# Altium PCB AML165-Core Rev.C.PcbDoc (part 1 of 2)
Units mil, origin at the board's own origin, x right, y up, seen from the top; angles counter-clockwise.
Board outline 3307.09 x 2047.24 mil, 2 copper layers (Top Layer, Bottom Layer), stack 12.8 mil thick; 150 components, 70 nets, 398 pads, 304 vias.
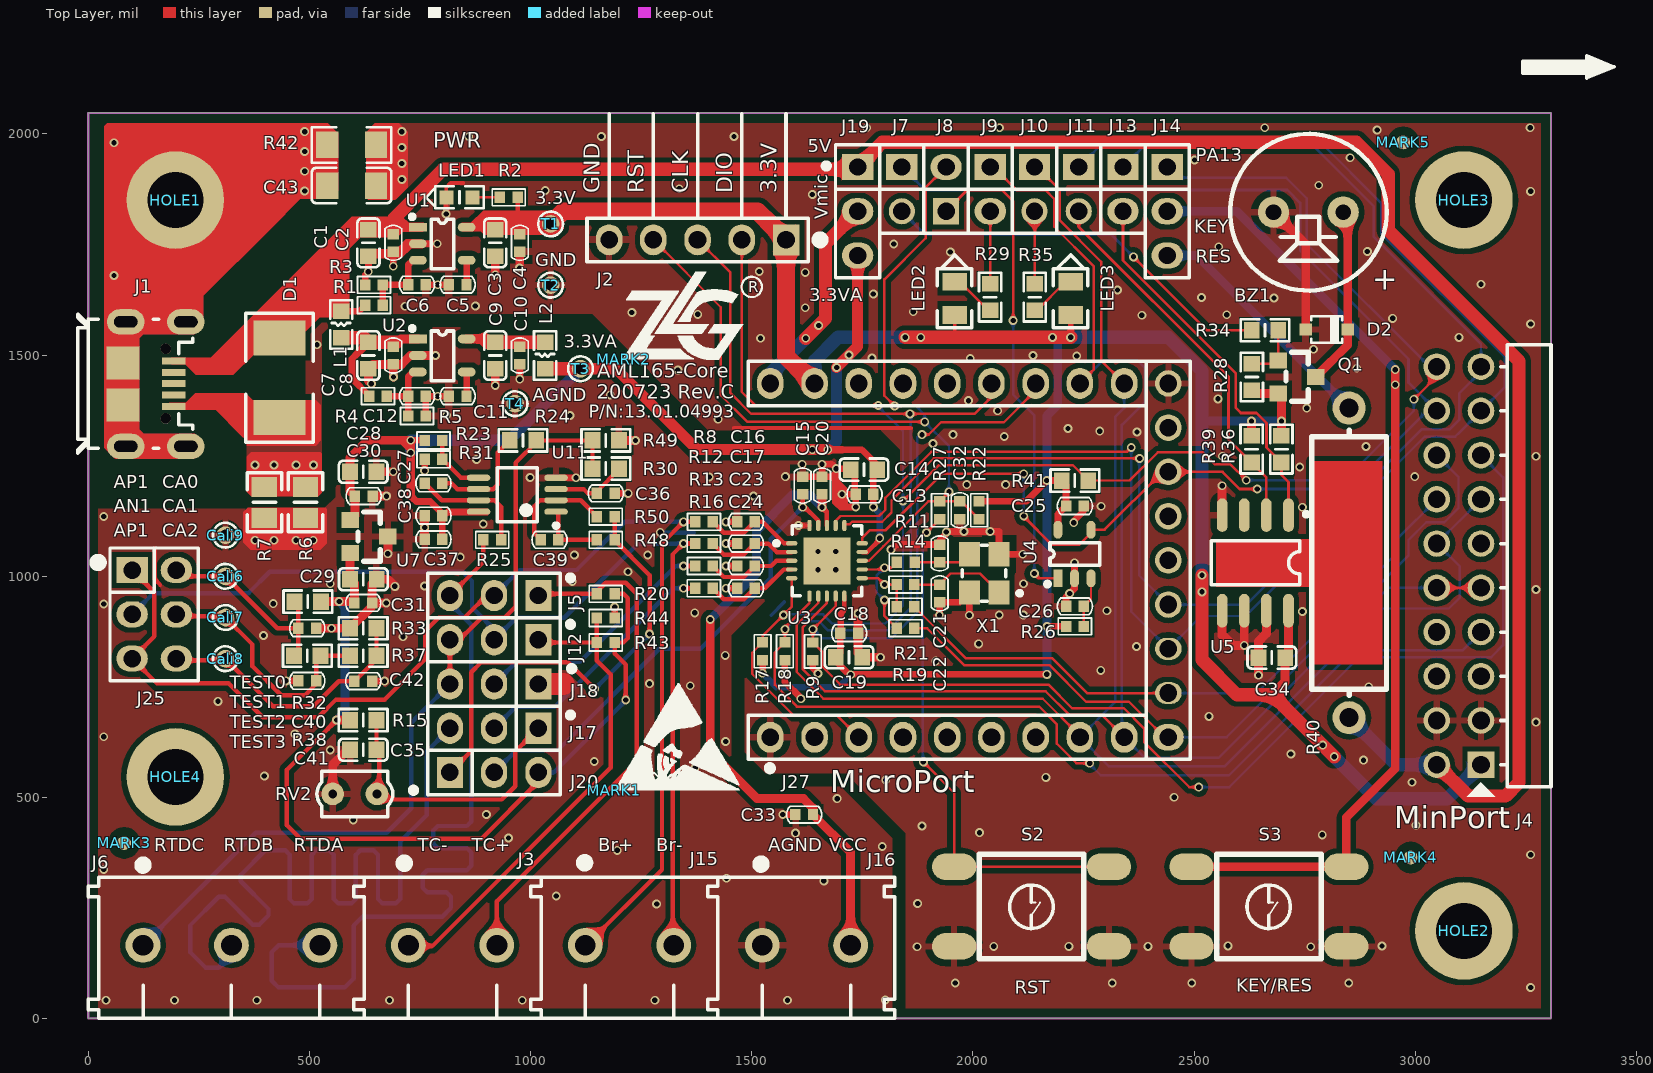
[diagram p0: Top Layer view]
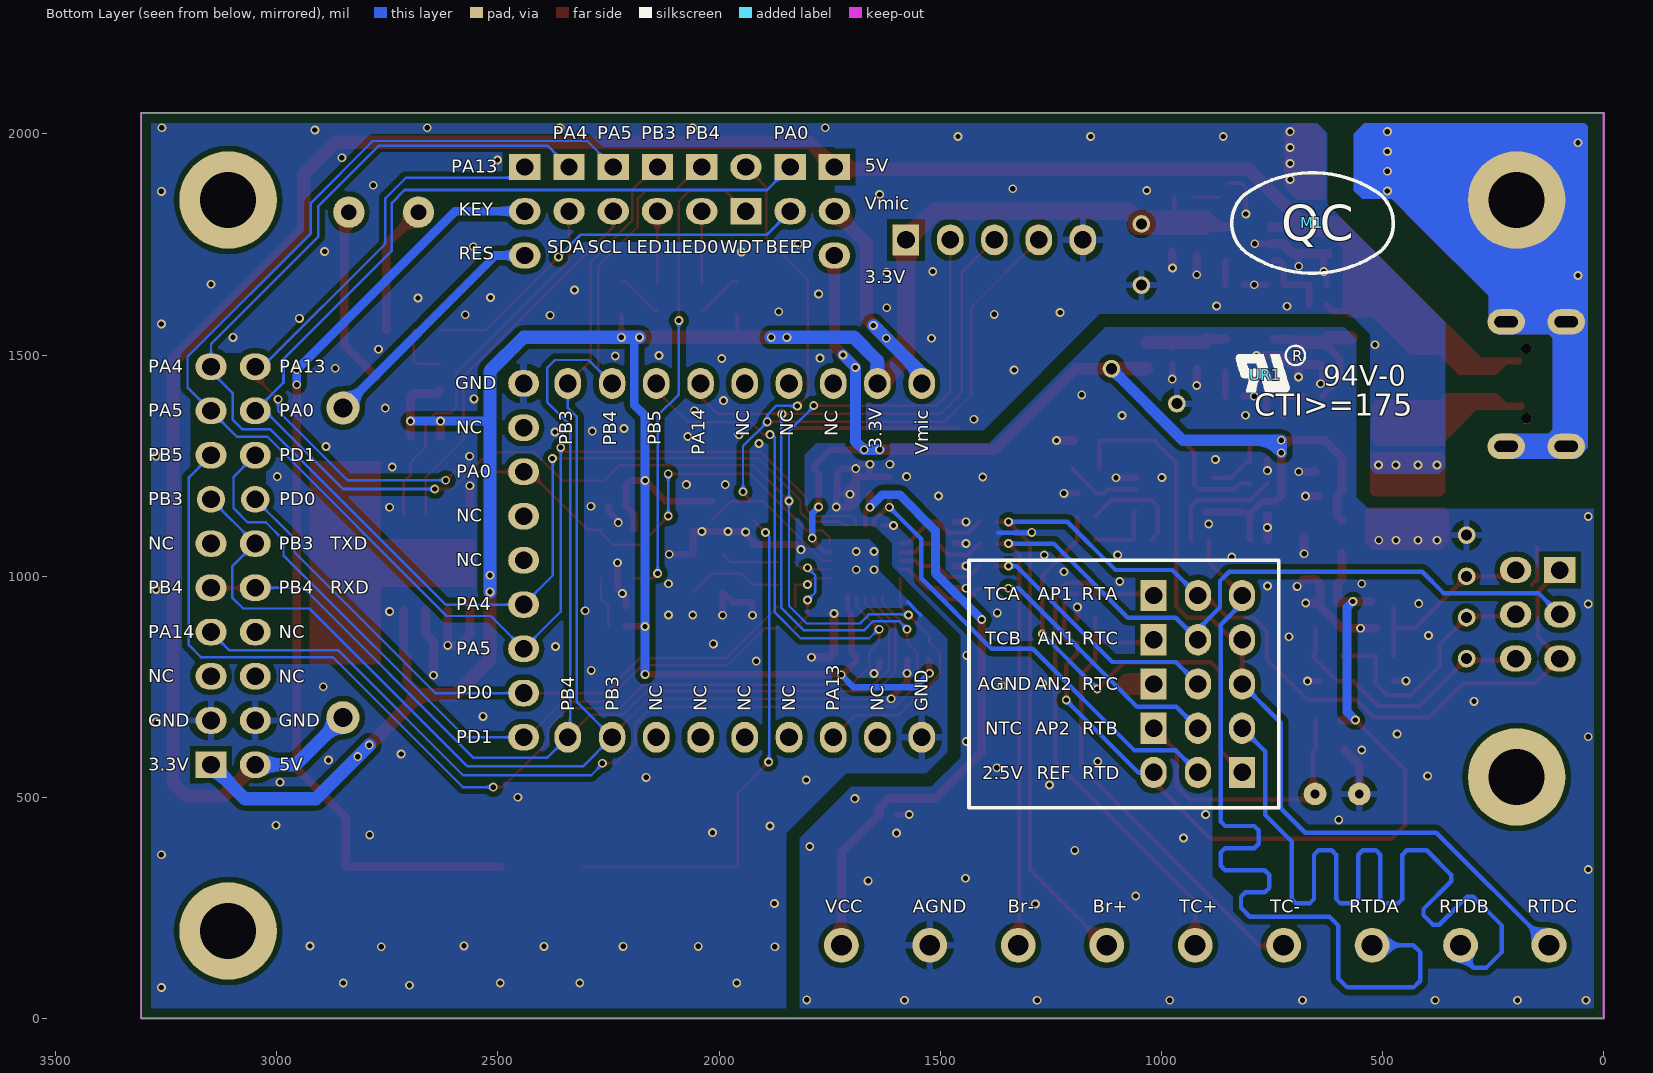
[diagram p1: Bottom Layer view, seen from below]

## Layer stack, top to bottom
Top Solder: solder mask 0.4, Solder Resist, Dk 3.5
Top Layer: signal copper 1.4
Dielectric 1: core 10, FR-4, Dk 4.2
Bottom Layer: signal copper 1.4
Bottom Solder: solder mask 0.4, Solder Resist, Dk 3.5

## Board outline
0,0 3307.09,0 3307.09,2047.24 0,2047.24

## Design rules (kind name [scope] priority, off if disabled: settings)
Clearance Clearance_Keepout [OnLayer('Keep-Out Layer')] p1: gap=20
Clearance Clearance_Manual [OnLayer('Bottom Layer') and IsSMTPin vs IsPadHoleValid>   ( HasFootprint('PAD-35/50') or   HasFootprint('HOLE-3.2') or HasFootprint('HOLE-3.2 - Screw') or   HasFootprint('HOLE4.22-SMT') or   HasFootprint('Mou Hole-300D450W310H-SMD') or     HasFootprint('AW6748') or  HasFootprint('IDCS80P500W-20X2-F')  )] p2: gap=50
Clearance Clearance_Via2Via [IsVia vs IsVia] p3: gap=6
Clearance Clearance_Poly2All [InPoly] p4: gap=12
Clearance Clearance_TP [HasFootprint('PAD-40') vs HasFootprint('PAD-40')] p5: gap=50
Clearance [All] p6: gap=5
DiffPairsRouting [All] p1: maxlimit=8 minlimit=8 mostfreqgap=8 toplayer_minwidth=5.1 toplayer_maxwidth=5.1 toplayer_prefwidth=5.1 bottomlayer_minwidth=5.1 bottomlayer_maxwidth=5.1 bottomlayer_prefwidth=5.1 maxuncoupledlength=500
HoleSize [All] p1: absolutevalues=TRUE maxlimit=1000 minlimit=1 maxpercent=80.000 minpercent=20.000
MinimumSolderMaskSliver [All] p1: minsoldermaskwidth=4
PlaneClearance PlaneClearance_Full [IsVia] p1: clearance=9
PlaneClearance [All] p2: clearance=20
PlaneConnect PlaneConnect_Full [IsVia] p1: planeconnectstyle=Direct reliefexpansion=20 reliefentries=4 reliefconductorwidth=10 reliefairgap=10
PlaneConnect [All] p2: planeconnectstyle=Relief reliefexpansion=10 reliefentries=4 reliefconductorwidth=15 reliefairgap=10
PolygonConnect PolygonConnect_SMDhole [HasFootprint('Mou Hole-300D450W310H-SMD') or HasFootprint('Mou Hole-373D600H-SMD')] p1: connectstyle=Relief reliefconductorwidth=80 reliefentries=4 polygonreliefangle="45 Angle" airgapwidth=20
PolygonConnect PolygonConnect_Full [IsVia or  HasFootprint('PAD-40') or   HasFootprint('PAD-35/50') or  HasFootprint('HOLE-3.2') or   HasFootprint('HOLE-3.2 - Screw')] p2: connectstyle=Direct reliefconductorwidth=10 reliefentries=4 polygonreliefangle="90 Angle" airgapwidth=10
PolygonConnect [All] p3: connectstyle=Relief reliefconductorwidth=15 reliefentries=4 polygonreliefangle="90 Angle" airgapwidth=15
RoutingVias [All] p1: holewidth=12 width=20 viastyle="Through Hole" minholewidth=12 minwidth=20 maxholewidth=12 maxwidth=20
SilkToSilkClearance [All] p1: silktosilkclearance=2
SilkToSolderMaskClearance [IsPad] p1: minsilkscreentomaskgap=2 clearancetoexposedcopper=TRUE
SolderMaskExpansion [All] p1: expansion=4
Width [All] p1: maxlimit=100 minlimit=5 preferedwidth=5
23 further rules are at their usual default settings.

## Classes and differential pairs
component class U_06: J4 J19 J27
component class U_03: C13 C14 C15 C16 C17 C18 C19 C20 C21 C22 C23 C24 C25 C26 C32 J2 J8 R8 R9 R11 R12 R13 R14 R16 R17 R18 R19 R21 R22 R26 R27 S2 U3 U4 X1
component class "01. MAIN": C43 HOLE1 HOLE2 HOLE3 HOLE4 M1 MARK1 MARK2 MARK3 MARK4 MARK5 R42 UR1
component class U_02: C1 C2 C3 C4 C5 C6 C7 C8 C9 C10 C11 C12 D1 J1 L1 L2 LED1 R1 R2 R3 R4 R5 R6 R7 T1 T2 T3 T4 U1 U2
component class U_05: BZ1 C34 D2 J7 J9 J10 J11 J13 J14 LED2 LED3 Q1 R28 R29 R34 R35 R36 R39 R40 R41 S3 U5
component class U_04: C27 C28 C29 C30 C31 C33 C35 C36 C37 C38 C39 C40 C41 C42 Cali6 Cali7 Cali8 Cali9 J3 J5 J6 J12 J15 J16 J20 J25 R15 R20 R23 R24 R25 R30 R31 R32 R33 R37 R38 R43 R44 R48 R49 R50 RV2 U7 U11
net class PWR: 3.3V 3.3VA 5V 5V/3.3VA AGND GND REF_2.5V

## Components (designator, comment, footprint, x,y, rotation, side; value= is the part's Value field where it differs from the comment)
BZ1 "BUZZER2" BUZZ-4/9 2758.55,1822.87 r180 top
C1 "10μF,10V,0603" 0603C 633.35,1753.5 r270 top
C2 "0.1μF,±10%" 0402C 689.49,1753.5 r90 top
C3 "10μF,10V,0603" 0603C 920,1753.5 r270 top
C4 "0.1μF,±10%" 0402C 975.52,1753.5 r90 top
C5 "0.1μF,±10%" 0402C 835,1659.02 r0 top
C6 "0.1μF,±10%" 0402C 742.97,1659.02 r180 top
C7 "10μF,10V,0603" 0603C 633.35,1498.91 r270 top
C8 "0.1μF,±10%" 0402C 689.49,1498.91 r90 top
C9 "10μF,10V,0603" 0603C 920,1498.91 r270 top
C10 "0.1μF,±10%" 0402C 975.52,1498.91 r90 top
C11 "0.1μF,±10%" 0402C 835,1406.84 r0 top
C12 "0.1μF,±10%" 0402C 742.97,1406.84 r180 top
C13 "0.1μF" 0402C 1755,1185.09 r0 top
C14 "16V,TDK,1uF" 0603C 1753.8,1240.91 r0 top
C15 "0.1μF" 0402C 1615,1204.7 r270 top
C16 "GCM155R71E104KE02D,0.1μF" 0402C 1486.91,1122.77 r0 top
C17 "GCM155R71E104KE02D,0.1μF" 0402C 1486.91,1073.68 r0 top
C18 "0.1μF" 0402C 1720.32,871.02 r180 top
C19 "16V,TDK,1uF" 0603C 1720,816.59 r180 top
C20 "0.1μF" 0402C 1659.04,1204.7 r270 top
C21 "12pF,±5%" 0402C 1924.82,1051.39 r90 top
C22 "12pF,±5%" 0402C 1924.82,961.02 r90 top
C23 "GCM155R71E104KE02D,0.1μF" 0402C 1486.91,1022.96 r0 top
C24 "GCM155R71E104KE02D,0.1μF" 0402C 1486.91,972.61 r0 top
C25 "0.1μF,±10%" 0402C 2230.63,1158.54 r180 top
C26 "0.1μF,±10%" 0402C 2230.63,931.8 r0 top
C27 "22pF,±5%" 0402C 780.37,1209.73 r180 top
C28 "10μF,6.3V" 0603C 621.57,1235.91 r180 top
C29 "10μF,6.3V" 0603C 621.78,992.81 r180 top
C30 "GCM155R71E104KE02D,0.1μF" 0402C 622.6,1180.83 r180 top
C31 "GCM155R71E104KE02D,0.1μF" 0402C 621.57,939.37 r180 top
C32 "0.1μF,±10%" 0402C 1970.16,1149.09 r270 top
C33 "GCM155R71E104KE02D,0.1μF" 0402C 1618.52,460.91 r0 top
C34 "C1608X7R1H104KT000N，104" 0603C 2675.91,815.91 r180 top
C35 "10μF" 0603C 621.57,607.61 r0 top
C36 "1μF,±10%" 0402C 1169.93,1187.09 r0 top
C37 "4.7μF" 0402C 780.37,1083.09 r180 top
C38 "0.1μF" 0402C 780.37,1136.89 r180 top
C39 "0.01μF,±10%" 0402C 1042.76,1082.09 r0 top
C40 "1μF,±10%" 0402C 495,882.28 r180 top
C41 "1μF,±10%" 0402C 495,763.28 r0 top
C42 "1μF,±10%" 0402C 621.57,762.63 r180 top
C43 "102,±10%" 1206C 595.2,1883.17 r180 top
Cali6 "TEST1" PAD-25/40 309.87,999.61 r180 top
Cali7 "TEST2" PAD-25/40 309.87,906.5 r180 top
Cali8 "TEST3" PAD-25/40 309.87,813.39 r180 top
Cali9 "TEST0" PAD-25/40 309.87,1092.72 r180 top
D1 "SMBJ6.5CA" SOD-1812 432.21,1448.54 r270 top
D2 "DIODE1" SOD-323 2800,1557.76 r0 top
HOLE1 "" HOLE-3.2 196.85,1850.39 r0 top locked
HOLE2 "" HOLE-3.2 3110.24,197.76 r0 top locked
HOLE3 "" HOLE-3.2 3110.24,1850.39 r0 top locked
HOLE4 "" HOLE-3.2 196.85,545.91 r0 top locked
J1 "ST-USB-002B-1,SMT" MICROUSB-ST-USB-002B-1 149.61,1434.25 r270 top locked
J2 "" SIP-5-2.54-6.0-R90 1377.48,1760.47 r180 top
J3 "DG127-5.08-02P-14-00AH,180°" CON508P1016L810W110D15S-2DIP 823.62,159.45 r0 top locked
J4 "HEADER 10X2" IDC-20-2.54-R90 3098.82,1023.62 r90 top locked
J5 "CON3" SIP-3-2.54 917.52,956.14 r180 top locked
J6 "DG127-5.08" CON508P1524L810W110D15S-3DIP 323.62,159.45 r0 top locked
J7 "BEEP" SIP-2-2.54#1 1839.37,1875 r270 top locked
J8 "" SIP-2-2.54#2 1939.37,1875 r90 top locked
J9 "LED0" SIP-2-2.54#3 2039.37,1875 r270 top locked
J10 "LED1" SIP-2-2.54#1 2139.37,1875 r270 top locked
J11 "SCL" SIP-2-2.54#1 2239.37,1875 r270 top locked
J12 "CON3" SIP-3-2.54 917.52,856.14 r180 top locked
J13 "SDA" SIP-2-2.54#3 2339.37,1875 r270 top locked
J14 "KEY" SIP-3-2.54 2439.37,1825 r270 top locked
J15 "DG127-5.08-02P-14-00AH,180°" CON508P1016L810W110D15S-2DIP 1223.62,159.45 r0 top locked
J16 "DG127-5.08-02P-14-00AH,180°" CON508P1016L810W110D15S-2DIP 1623.62,159.45 r0 top locked
J17 "CON3" SIP-3-2.54 917.52,656.14 r180 top
J18 "CON3" SIP-3-2.54 917.52,756.14 r180 top
J19 "" SIP-3-2.54 1739.37,1825 r270 top
J20 "CON3" SIP-3-2.54 917.52,556.14 r0 top locked
J25 "HEADER 3X2" IDC-6-2.54 149,913.62 r270 top
J27 "3X7Inter" "SIP-27 2.54C" 1991.98,1035.7 r90 top locked
L1 "40Ω,3A" 0603L 571.87,1568.91 r270 top
L2 "40Ω,3A" 0603L 1032.76,1498.91 r270 top
LED1 "0603QRC,红色" LED-0603 839.24,1856.54 r180 top
LED2 "LED0" LED-0805 1958.78,1628.24 r90 top
LED3 "LED1" LED-0805 2221,1628.24 r90 top
M1 "ZY QC" ZY_QC 658.35,1798.5 r180 bottom
MARK1 "ESD-MARK" ZY_ESD-7 1189,515.91 r0 top
MARK2 "ZLG" ZLG0.7 1211,1490.91 r0 top
MARK3 "MARKER" MARKER-C-0.8M 81,396.91 r90 top
MARK4 "MARKER" MARKER-C-0.8M 2990,363.91 r0 top
MARK5 "MARKER" MARKER-C-0.8M 2973,1980.91 r90 top
Q1 "PNP-1" SOT-23 2733,1450.59 r0 top
R1 "20KΩ,±0.5%" 0402R 646,1612.54 r0 top
R2 "2K,±5%" 0402R 950.57,1856.54 r0 top
R3 "20KΩ,±0.5%" 0402R 646.03,1658.46 r180 top
R4 "20KΩ,±0.5%" 0402R 655,1406.84 r0 top
R5 "20KΩ,±0.5%" 0402R 743.12,1362 r0 top
R6 "0Ω" 0805R 491.26,1166.92 r270 top
R7 "0Ω" 0805R 397.88,1166.92 r270 top
R8 "1K,±1%" 0402R 1391.91,1122.77 r0 top
R9 "RTT02103JTH,10K" 0402R 1638.2,830 r90 top
R11 "RTT02000JTH,0Ω" 0402R 1848.35,1031.39 r0 top
R12 "1K,±1%" 0402R 1391.76,1073.68 r0 top
R13 "1K,±1%" 0402R 1391.91,1022.93 r0 top
R14 "RTT02000JTH,0Ω" 0402R 1847.56,980.91 r180 top
R15 "10KΩ,1/16W" 0603R 621.57,674.61 r180 top
R16 "1K,±1%" 0402R 1391.76,972.61 r0 top
R17 "RTT02103JTH,10K" 0402R 1524.48,830.32 r90 top
R18 "RTT02103JTH,10K" 0402R 1575,830.32 r270 top
R19 "RTT02000JTH,0Ω" 0402R 1847.56,882.28 r180 top
R20 "10M,±5%" 0402R 1170,960 r180 top
R21 "RTT02000JTH,0Ω" 0402R 1847.56,930.91 r180 top
R22 "RTT02103JTH,10K" 0402R 2014,1149.09 r90 top
R23 "12K,±5%" 0402R 780.37,1306.77 r0 top
R24 "4.7KΩ" 0603R 982.85,1306.77 r0 top
R25 "100Ω,±1%" 0402R 913.35,1082.09 r0 top
R26 "RTT02103JTH,10K" 0402R 2230.63,886.29 r180 top
R27 "10Ω,±1%" 0402R 1925.26,1149.09 r90 top
R28 "10KΩ,±1%" 0603R 2630.91,1450.41 r270 top
R29 "1.5KΩ" 0603R 2038.78,1630.91 r90 top
R30 "47KΩ" 0603R 1169.93,1243.09 r0 top
R31 "20KΩ,±0.5%" 0402R 780.37,1264.25 r0 top
R32 "20KΩ,1/16W" 0603R 496.16,942.61 r0 top
R33 "20KΩ,1/16W" 0603R 621.57,882.28 r180 top
R34 "1.5KΩ" 0603R 2660.44,1555.91 r0 top
R35 "1.5KΩ" 0603R 2140,1630.91 r90 top
R36 "10KΩ,±1%" 0603R 2697.68,1287.09 r90 top
R37 "499Ω" 0603R 621.57,819.91 r180 top
R38 "51Ω,10ppm" 0603R 495,819.91 r0 top
R39 "10KΩ,±1%" 0603R 2630,1287.09 r90 top
R40 "20Ω,±5%" RESAD1778W80L1450D430P 2850.63,1030 r90 top
R41 "4.7KΩ" 0603R 2230.63,1216.2 r180 top
R42 "1MΩ" 1206R 595.2,1974.96 r180 top
R43 "1K,±1%" 0402R 1170,850 r0 top
R44 "1K,±1%" 0402R 1170,905.29 r0 top
R48 "200Ω,±1%" 0402R 1169.93,1082.09 r0 top
R49 "2KΩ" 0603R 1169.93,1306.77 r0 top
R50 "100Ω,±0.5%" 0402R 1169.93,1134.59 r180 top
RV2 "103AP2" RESRR254W35L380T260H850P 602.57,507.61 r0 top
S2 "6×6×5.0mm" KEY-6S 2132.6,253 r180 top
S3 "KEY/RES" KEY-6S 2669.25,253 r180 top
T1 "3.3V" PAD-25/40 1045.34,1796.34 r0 top
T2 "GND" PAD-25/40 1045.34,1657.91 r0 top
T3 "3.3VA" PAD-25/40 1112.85,1468.91 r0 top
T4 "AGND" PAD-25/40 965,1389.91 r0 top
U1 "ZL6205A33TS5" SOT-23-5 800.21,1751.54 r0 top
U2 "ZL6205A33TS5" SOT-23-5 800.21,1498.91 r0 top
U3 "ZML165N20A" QFN50P400X400X85-21N 1670,1034.77 r0 top
U4 "CAT823STDI-GT3" SOT-23-5 2229.72,1049.93 r90 top
U5 "LM75B" SOIC127P600X175-8N 2638.63,1030 r270 top
U7 "REF3325AIDBZR" SOT-23 634.82,1089.43 r0 top
U11 "TP5592-VR" SOP65P490X120-8N 969.93,1184.09 r180 top
UR1 "UR" ZY_UR-3X2 765,1455.91 r180 bottom
X1 "JYD3A1C7G5-12.5-16.000,16.0000MHz" OSCCC250X320X80-4N 2025.57,1006.32 r90 top

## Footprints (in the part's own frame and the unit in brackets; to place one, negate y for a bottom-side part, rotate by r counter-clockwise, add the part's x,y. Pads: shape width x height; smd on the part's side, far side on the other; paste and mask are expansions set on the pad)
0402C [mm]
  rect 0.6x0.65 smd mask+0.025: 1(-0.508,0) 2(0.508,0)
  silkscreen extent -1.01,-0.48 1.01,0.48, body extent -0.51,-0.23 0.49,0.27, height 0.5
0402R [mm]
  rect 0.6x0.65 smd mask+0.025: 1(-0.508,0) 2(0.508,0)
  silkscreen extent -0.95,-0.48 0.95,0.48, body extent -0.47,-0.25 0.53,0.25, height 0.35
0603C [mm]
  rect 0.9x0.95 smd: 1(-0.762,0) 2(0.762,0)
  silkscreen extent -1.4,-0.64 1.4,0.64, body extent -0.79,-0.38 0.81,0.42, height 0.3
0603L [mm] "Chip Inductor, 2-Leads, Body 2.50x2.00mm, IPC Medium Density"
  rect 0.9x0.95 smd: 1(-0.762,0) 2(0.762,0)
  silkscreen extent -1.4,-0.64 1.4,0.64, body extent -0.8,-0.4 0.8,0.4, height 0.3
0603R [mm]
  rect 0.9x0.95 smd: 1(-0.762,0) 2(0.762,0)
  silkscreen extent -1.4,-0.64 1.4,0.64, body extent -0.8,-0.4 0.8,0.4, height 0.3
0805R [mm]
  rect 1.15x1.45 smd: 1(-0.889,0) 2(0.889,0)
  silkscreen extent -1.7,-0.99 1.7,0.99, body extent -1,-0.63 1,0.63, height 0.78
1206C [mil] "元件 长X宽=120X60mil"
  rect 50x60 smd: 1(-55,0) 2(55,0)
  silkscreen extent -90,-40 90,40, body extent -62,-32 64,31, height 39
1206R [mil] "元件 长X宽=120X60mil"
  rect 50x60 smd: 1(-55,0) 2(55,0)
  silkscreen extent -90,-40 90,40, body extent -63,-31 63,31, height 24
BUZZ-4/9 [mm]
  round 1.8 hole 0.9: 1(-2,0) 2(2,0)
  silkscreen extent -4.5,-4.5 4.5,4.5
CON508P1016L810W110D15S-2DIP [mm]
  round 2 hole 1.2: 1(-2.54,0.15) 2(2.54,0.15)
  silkscreen extent -5.68,-4.05 5.08,5.11
CON508P1524L810W110D15S-3DIP [mm]
  round 2 hole 1.2: 1(-5.08,0.15) 2(0,0.15) 3(5.08,0.15)
  silkscreen extent -8.22,-4.05 7.62,5
HOLE-3.2 [mm]
  round 5.6 hole 3.2: 1(0,0)
IDC-6-2.54 [mm]
  rect 1.5x1.8 hole 1: 1(-2.54,-1.27)
  oval 1.5x1.8 hole 1: 2(-2.54,1.27) 3(0,-1.27) 4(0,1.27) 5(2.54,-1.27) 6(2.54,1.27)
  silkscreen extent -3.81,-3.47 3.81,2.54, body extent -3.81,-2.54 3.81,2.54, height 7.58
IDC-20-2.54-R90 [mil]
  rect 60x60 / inner rect 60x70 / far side rect 60x70 hole 40: 1(-450,-50)
  round 60 / inner oval 60x70 / far side oval 60x70 hole 40: 2(-450,50) 3(-350,-50) 4(-350,50) 5(-250,-50) 6(-250,50) 7(-150,-50) 8(-150,50) 9(-50,-50) 10(-50,50) 11(50,-50) 12(50,50) 15(250,-50) 16(250,50) 17(350,-50) 18(350,50) 19(450,-50) 20(450,50)
  round 60 / inner round 60 / far side oval 60x64 hole 40: 13(150,-50) 14(150,50)
  silkscreen extent -523,-208 500,-17
KEY-6S [mil]
  oval 100x60 smd: 1(-175,90) 2(-175,-90) 3(175,-90) 4(175,90)
  silkscreen extent -118,-118 118,118, body extent -201,-122 201,122, height 268
LED-0603 [mm] "20100324  贴片0603LED   LSB"
  rect 0.8x0.8 smd: 1(-0.75,0) 2(0.75,0)
  silkscreen extent -1.4,-0.64 1.93,0.64, body extent -0.8,-0.4 0.8,0.4, height 0.4
LED-0805 [mm] "170907内距改0.9mm"
  rect 1.014x1.4 smd: 1(-0.957,0) 2(0.957,0)
  silkscreen extent -1.7,-0.99 2.49,0.99, body extent -1,-0.64 1,0.64, height 1.1
MARKER-C-0.8M [mm]
  round 0.8 smd paste-1.016 mask+0.4: 0(0,0)
  Top Layer pour cut-out: -0.9,0 -0.831,-0.344 -0.636,-0.636 -0.344,-0.831 0,-0.9 0,-0.9 0.344,-0.831 0.636,-0.636 0.831,-0.344 0.9,0 0.9,0 0.831,0.344 0.636,0.636 0.344,0.831 0,0.9 0,0.9 -0.344,0.831 -0.636,0.636 -0.831,0.344 -0.9,0
MICROUSB-ST-USB-002B-1 [mm]
  oval 1.45x2.15 on Top Paste: 0(-3.575,-1.65) 0(-3.575,1.8) 0(3.575,-1.65) 0(3.575,1.8)
  round 0.6 hole 0.6 unplated: 0(-2.025,0.65) 0(1.975,0.65)
  rect 0.4x1.35 smd: 1(-1.325,1.115) 2(-0.675,1.115) 3(-0.025,1.115) 4(0.625,1.115) 5(1.275,1.115)
  oval 1.45x2.15 hole 0.65 slot 1.35 at 90 deg: 6(-3.575,1.8) 7(3.575,1.8) 8(-3.575,-1.65) 9(3.575,-1.65)
  rect 1.9x1.9 smd: 10(-1.2,-1.8) 11(1.2,-1.8)
  silkscreen extent -4.02,-4.4 3.98,2.2
OSCCC250X320X80-4N [mm]
  rect 1.4x1.2 smd: 1(-1.1,-0.85) 2(1.1,-0.85) 3(1.1,0.85) 4(-1.1,0.85)
  silkscreen extent -1.6,-2.16 1.6,1.25
PAD-25/40 [mil]
  round 40 hole 25: 1(0,0)
  silkscreen extent -28,-28 28,28
QFN50P400X400X85-21N [mm] "QFN, 20-Leads, Body 4.0x4.0mm (max), Pitch 0.50mm, IPC Medium Density"
  oval 0.65x0.25 smd: 1(-2.025,1) 2(-2.025,0.5) 3(-2.025,0) 4(-2.025,-0.5) 5(-2.025,-1) 11(2.025,-1) 12(2.025,-0.5) 13(2.025,0) 14(2.025,0.5) 15(2.025,1)
  oval 0.25x0.65 smd: 6(-1,-2.025) 7(-0.5,-2.025) 8(0,-2.025) 9(0.5,-2.025) 10(1,-2.025) 16(1,2.025) 17(0.5,2.025) 18(0,2.025) 19(-0.5,2.025) 20(-1,2.025)
  rect 2.7x2.7 smd: 21(0,0)
  silkscreen extent -3.02,-2 2,2, body extent -2,-2 2,2, height 0.85
RESAD1778W80L1450D430P [mm]
  round 1.9 hole 1.1: 1(-8.89,0) 2(8.89,0)
  silkscreen extent -7.62,-2.15 7.62,2.15
RESRR254W35L380T260H850P [mm]
  round 1.3 hole 0.5: 1(-1.27,0) 2(1.27,0)
  silkscreen extent -2.18,-1.3 2.18,1.3
SIP-2-2.54#1 [mm]
  rect 1.5x1.8 hole 1: 1(-1.27,0)
  round 1.5 / inner oval 1.5x1.8 / far side oval 1.5x1.8 hole 1: 2(1.27,0)
  silkscreen extent -2.54,-1.27 2.54,1.27, body extent -2.54,-1.27 2.54,1.27, height 7.58
SIP-2-2.54#2 [mm]
  rect 1.5x1.5 / inner rect 1.5x1.8 / far side rect 1.5x1.8 hole 1: 1(-1.27,0)
  oval 1.5x1.8 hole 1: 2(1.27,0)
  silkscreen extent -2.54,-1.27 2.54,1.27, body extent -2.54,-1.27 2.54,1.27, height 7.58
SIP-2-2.54#3 [mm]
  rect 1.5x1.8 hole 1: 1(-1.27,0)
  oval 1.5x1.8 hole 1: 2(1.27,0)
  silkscreen extent -2.54,-1.27 2.54,1.27, body extent -2.54,-1.27 2.54,1.27, height 7.58
SIP-3-2.54 [mm]
  rect 1.5x1.8 hole 1: 1(-2.54,0)
  oval 1.5x1.8 hole 1: 2(0,0) 3(2.54,0)
  silkscreen extent -4.51,-1.27 3.81,1.27, body extent -3.81,-1.27 3.81,1.27, height 7.58
SIP-5-2.54-6.0-R90 [mil] "引脚伸出部分为6.0mm"
  rect 60x70 hole 40: 1(-200,0)
  oval 60x70 hole 40: 2(-100,0) 3(0,0) 4(100,0) 5(200,0)
  silkscreen extent -286,-285 250,49
"SIP-27 2.54C" [mil]
  oval 70x60 hole 40: 1(-400,450) 2(-400,350) 3(-400,250) 4(-400,150) 5(-400,50) 6(-400,-50) 7(-400,-150) 8(-400,-250) 9(-400,-350) 19(400,-350) 20(400,-250) 21(400,-150) 22(400,-50) 23(400,50) 24(400,150) 25(400,250) 26(400,350) 27(400,450)
  oval 60x70 hole 40: 10(-400,-450)
  oval 50x60 / inner oval 60x70 / far side oval 60x70 hole 40: 11(-300,-450) 12(-200,-450)
  round 60 / inner oval 60x70 / far side oval 60x70 hole 40: 13(-100,-450) 14(0,-450) 15(100,-450) 16(200,-450) 17(300,-450) 18(400,-450)
  silkscreen extent -476,-500 450,500
SOD-323 [mil]
  rect 28x28 smd: 1(-47.5,0) 2(47.5,0)
  silkscreen extent -35,-30 35,30, body extent -51,-26 51,25, height 39
SOD-1812 [mm]
  rect 2x3 smd: 1(-2.286,0) 2(2.286,0)
  Top Layer pour cut-out: -1.27,1.499 -1.27,-1.499 1.245,-1.499 1.245,1.499
  silkscreen extent -3.71,-1.93 3.71,1.93
SOIC127P600X175-8N [mil]
  oval 76.06x24 smd: 1(-108.03,75) 2(-108.03,25) 3(-108.03,-25) 4(-108.03,-75) 5(108.03,-75) 6(108.03,-25) 7(108.03,25) 8(108.03,75)
  silkscreen extent -115,-100 50,120, body extent -118,-96 118,97, height 61
SOP65P490X120-8N [mm] "TSOP, 8-Leads, Body 3.00x3.00mm, Pitch 0.65mm, IPC Medium Density"
  oval 1.35x0.35 smd: 1(-2.225,0.975) 2(-2.225,0.325) 3(-2.225,-0.325) 4(-2.225,-0.975) 5(2.225,-0.975) 6(2.225,-0.325) 7(2.225,0.325) 8(2.225,0.975)
  silkscreen extent -2.35,-1.55 1.15,1.9, body extent -1.55,-1.55 1.55,1.55, height 1.2
SOT-23 [mil]
  rect 40x36 smd: 1(-42.5,37.4) 2(-42.5,-37.4) 3(42.5,0)
  silkscreen extent -25,-56 25,56, body extent -47,-57 50,58, height 39
SOT-23-5 [mil]
  rect 40x20 smd: 1(-55,37.4)
  oval 40x20 smd: 2(-55,0) 3(-55,-37.4) 4(55,-37.4) 5(55,37.4)
  silkscreen extent -73,-57 26,66, body extent -55,-57 55,57, height 43
ZLG0.7 [mil] "7.8mmX5.6mm     不是太标准"
  silkscreen extent -2,0 312,197
ZY_ESD-7 [mil]
  silkscreen extent 1,1 284,242
ZY_QC [mil]
  silkscreen extent -183,-114 183,114
ZY_UR-3X2 [mil]
  silkscreen extent -67,-40 90,65

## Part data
BZ1: library part 1.06.09.0016, "Buzzer有极性"
C1 C3 C7 C9: library part 02.01.00456, "GRM188D71A106MA73D,0603,Murata,10μF,X7T,±20%,10V"
C2 C4 C5 C6 C8 C10 C11 C12: library part 1.02.17.0020, "GRM155R61E104KA87D,0.1μF,±10%,25V,X5R,0402,muRata,RoHS"
C13 C15 C16 C17 C18 C20 C23 C24 C30 C31 C33 C38: library part 1.02.17.0118, "GCM155R71E104KE02D,0.1μF,±10%,25V,X7R,0402,muRata,RoHS"
C14 C19: library part 02.01.00365, "CGA3E1X7R1C105KT0Y0N,1uF,±10%,16V,X7R,0603,TDK,"
C21 C22: library part 1.02.17.0018, "GRM1555C1H120JA01D,12pF,±5%,50V,C0G,0402,muRata,RoHS"
C25 C26 C32: library part 1.02.17.0006, "GRM155R71C104KA88D,0.1μF,±10%,16V,X7R,0402,muRata,RoHS"
C27: library part 1.02.17.0036, "GRM1555C1H220JA01D,22pF,±5%,50V,C0G,0402,muRata,RoHS"
C28 C29 C35: library part 1.02.01.0065, "10μF,6.3V,X5R,GRM188R60J106M****,0603,Murata,RoHS"
C34: library part 1.02.01.0072, "C1608X7R1H104KT000N，104，±10%，50V，X7R,TDK,0603,RoHS"
C36 C40 C41 C42: library part 1.02.17.0092, "GRM155R61C105KA12D,1μF,±10% ,16V,X5R,0402,muRata,RoHS"
C37: library part 1.02.17.0073, "GRM155R60J475ME87D,4.7μF,±20%,6.3V,X5R,0402,muRata,RoHS"
C39: library part 1.02.17.0019, "GRM155R71H103KA88D,0.01μF,±10%,50V,X7R,0402,muRata,RoHS"
C43: library part 1.02.03.0003, "102,±10%,2KV,X7R,1206,*,RoHS"
Cali6 Cali7 Cali8 Cali9 T1 T2 T3 T4: library part TEST-DOT
D1: library part 1.04.03.0003, "SMBJ6.5CA,DO-214AA,君耀,RoHS"
D2: library part 1.04.07.0027, "1N4148,SOD-323,RoHS"
HOLE1 HOLE2 HOLE3 HOLE4: library part "HOLE - 不上螺丝"
J1: library part 20.02.00033, "ST-USB-002B-1,SMT,SUNGTECH,MicroUSB-A"
J2: library part CON5, "Connector"
J3 J15 J16: library part 1.10.06.0070, "DG127-5.08-02P-14-00AH,180°,绿色,DEGSON,RoHS"
J5 J12 J17 J18 J20: "Connector"
J6: library part 19.04.00251, "DG127-5.08-03P-14-00AH,180°,绿色,THT"
J7 J8 J9 J10 J11 J13: library part CON2, "Connector"
J14 J19: library part CON3, "Connector"
L1 L2: library part 1.03.03.0011, "40Ω,3A,DCR35mΩ,BH03Y314S-40R,SMD,0603,丰晶,RoHS"
LED1: library part 1.04.05.0008, "0603QRC,红色,0603,创光,RoHS"
LED2 LED3: library part 1.04.05.0002, "绿色,0805,0805,RoHS"
Q1: library part 1.04.09.0002, "PNP Transistor"
R1 R3 R4 R5 R31: library part 1.01.17.0053, "20KΩ,±0.5%,0402,RoHS"
R2: library part 1.01.17.0032, "2K,±5%,0402,RALEC,RoHS"
R6 R7: library part 1.01.02.0001, "0Ω,0805,*,RoHS"
R8 R12 R13 R16 R43 R44: library part 1.01.17.0016, "1K,±1%,0402,RALEC,RoHS"
R9 R17 R18 R22 R26: library part 1.01.17.0006, "RTT02103JTH,10K,±5%,0402,RALEC,RoHS"
R11 R14 R19 R21: library part 1.01.17.0004, "RTT02000JTH,0Ω,±5%,0402,RALEC,RoHS"
R15: library part 1.01.01.0192, "10KΩ,1/16W,10PPM/℃,±0.1%,0603,Viking,RoHS"
R20: library part 1.01.17.0005, "10M,±5%,0402,RALEC,RoHS"
R23: library part 1.01.17.0035, "12K,±5%,0402,RALEC,RoHS"
R24 R41: library part 1.01.01.0045, "4.7KΩ,0603,*,RoHS"
R25: library part 1.01.17.0029, "100Ω,±1%,0402,RALEC,RoHS"
R27: library part 1.01.17.0059, "10Ω,±1%,1/16W,0402,RoHS"
R28 R36 R39: library part 1.01.01.0052, "10KΩ,±1%,0603,*,RoHS"
R29 R34 R35: library part 1.01.01.0037, "1.5KΩ,0603,*,RoHS"
R30: library part 1.01.01.0060, "47KΩ,0603,*,RoHS"
R32 R33: library part 1.01.01.0207, "20KΩ,1/16W,10PPM/℃,±0.1%,0603,Viking,RoHS"
R37: library part 1.01.01.0155, "499Ω,RN731JTTD,4990B10,0603,KOA,RoHS"
R38: library part 1.01.01.0215, "51Ω,10ppm,±0.1%,AR03BTB0510,0603,Viking,RoHS"
R40: library part 1.01.10.0003, "20Ω,±5%,2W,Ф5.5×16mm,RoHS"
R42: library part 1.01.03.0019
R48: library part 1.01.17.0073, "200Ω,±1%,0402,RoHS"
R49: library part 1.01.01.0157, "2KΩ,RN731JTTD,2001B10,0603,KOA,RoHS"
R50: library part 1.01.17.0052, "100Ω,±0.5%,0402,RoHS"
RV2: library part 1.01.14.0020, "103AP2,SIP,semitec,RoHS"
S2: library part 1.09.01.0003, "TS0641-0501B,6×6×5.0mm,黑色,SMD,卷带装,RoHS"
S3: library part 1.09.01.0003, "6×6×5.0mm,黑色,SMD,,*"
U1 U2: library part 08.09.03069, "ZL6205A33TS5,SOT-23-5,ZLG"
U3: library part 89.12.00028
U4: library part CAT823, "1.05.07.0025"
U5: library part 1.05.10.0602, "LM75BD,SO-9,NXP,RoHS"
U7: library part 1.05.10.0334, "REF3325AIDBZR,SOT-23,TI"
U11: library part 1.05.20.0102, "TP5592-VR,MSOP-8,3PEAK,RoHS"
X1: library part 1.07.03.0077, "JYD3A1C7G5-12.5-16.000,16.0000MHz,±10ppm,12.5pF,-40~85℃,SMD3225,JYEG,RoHS"

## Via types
v1: diameter 20, hole 12, Top Layer to Bottom Layer, tented both sides, 304 vias

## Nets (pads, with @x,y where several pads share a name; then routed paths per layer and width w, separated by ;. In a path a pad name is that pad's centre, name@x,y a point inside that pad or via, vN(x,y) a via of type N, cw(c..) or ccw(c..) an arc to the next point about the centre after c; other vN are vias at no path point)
3.3V: C3.1 C4.2 C18.2 C19.2 C25.2 C34.1 J2.1 J4.1 J27.26 LED2.1 LED3.1 Q1.2 R2.2 R17.1 R22.2 R26.2 R28.2 R36.2 R39.2 R41.2 T1.1 U1.5 U3.10 U4.5 U5.8 | length 6262.8
  Top Layer w8: 1959,1539.91 1958.78,1540.13 LED2.1@1958.78,1590.57 LED2.1@1964.34,1590.57
  Top Layer w10: 970.57,1818.19 R2.2@970.57,1856.54 ; 1701.5,915 1709.37,922.87 U3.10@1709.37,955.05 ; v1(2221,1539.91) LED3.1@2221,1590.57
  Top Layer w15: v1(1524.48,780.43) R17.1@1524.48,810.32 ; 1701.5,915 1701.5,872.2 C18.2@1700.32,871.02 1700.32,826.91 C19.2@1690,816.59 1690,807.91 v1@1720,777.91 ; v1@1724,777.91 v1(2167.29,777.91) ; R22.2@2014,1169.09 2120.18,1169.09 v1(2167.29,1216.2) R41.2@2200.63,1216.2 2210.63,1206.2 C25.2@2210.63,1158.54 2192.32,1140.23 U4.5@2192.32,1104.93 ; v1(2167.39,886.29) R26.2@2210.63,886.29 ; R28.2@2630,1419.5 R28.2@2630.91,1420.41
  Top Layer w20: R39.2@2630,1317.09 v1(2630,1350.41) ; R28.2@2630.91,1420.41 2638.13,1413.19 Q1.2@2690.5,1413.19 2697.68,1406 v1(2697.68,1350.41) R36.2@2697.68,1317.09 ; 2677,731.91 2705.91,760.81 C34.1@2705.91,815.91 2713.63,823.63 U5.8@2713.63,921.97
  Top Layer w30: v1(1846.75,1539.91) v1(1882,1539.91) 1959,1539.91 v1(2180,1539.91) v1(2221,1539.91) ; v1(2518,1001.91) v1(2518,964.45) 2518,810.91 2597,731.91 2677,731.91 v1(2791,617.91) v1(2817,591.91)
  Top Layer w40: T1.1@1045.34,1796.34 1073.9,1824.91 1513.05,1824.91 J2.1@1577.48,1760.47 1577.48,1497.43 1639.21,1435.7 J27.26@1641.98,1435.7
  Bottom Layer w15: v1(1524.48,780.43) 1556,748.91 1696,748.91 v1(1724,776.91)
  Bottom Layer w20: v1(2167.29,777.91) v1(2167.29,1216.2) 2167.29,1362.2 2192,1386.91 2192,1535.91 ; 2518,1350.91 2518.5,1350.41 v1(2630,1350.41) v1(2697.68,1350.41)
  Bottom Layer w30: J27.26@1641.98,1435.7 1641.98,1486.88 1695,1539.91 v1(1846.75,1539.91) v1(1882,1539.91) ; v1(2180,1539.91) v1(2221,1539.91) 2442,1539.91 2518,1463.91 2518,1350.91 v1(2518,1001.91) v1(2518,964.45) ; v1(2791,617.91) v1(2817,591.91) 2912,496.91 3072.1,496.91 J4.1@3148.82,573.62
3.3VA: C13.2 C14.2 C28.2 C30.2 C37.1 C38.1 J19.3 L2.2 R23.1 T3.1 U3.14 U7.1 U11.8 | length 2868.2
  Top Layer w10: U3.14@1749.72,1054.46 1761.46,1054.46 1789.5,1082.5 v1(1789.5,1085.91)
  Top Layer w15: 728.85,1181.96 741.96,1168.85 772.96,1168.85 800.37,1141.44 C38.1@800.37,1136.89 ; v1(728.85,1307.21) 759.93,1307.21 R23.1@760.37,1306.77 ; C37.1@800.37,1083.09 C38.1@800.37,1136.89 ; U11.8@900.85,1144.89 812.76,1144.89 804.76,1136.89 C38.1@800.37,1136.89 ; v1(1672,1285.91) 1749,1285.91 1783.8,1251.11 C14.2@1783.8,1240.91 1775,1232.11 C13.2@1775,1185.09 v1(1775,1156.45)
  Top Layer w20: U7.1@592.32,1126.83 602.6,1137.11 C30.2@602.6,1180.83 591.57,1191.86 C28.2@591.57,1235.91 591.57,1267.47 631.3,1307.21 711,1307.21 ; 728.85,1181.96 v1(728.85,1278.91) 728.85,1289.36 ; 711,1307.21 v1(728.85,1307.21) 728.85,1289.36 ; 711,1307.21 728.85,1289.36
  Top Layer w25: T3.1@1112.85,1468.91 1193,1468.91 1376,1285.91 v1(1637,1285.91) v1(1672,1285.91) ; v1(1692,1471.91) v1(1720,1499.91) 1739.37,1519.27 J19.3@1739.37,1725
  Top Layer w30: L2.2@1032.76,1468.91 T3.1@1112.85,1468.91
  Bottom Layer w15: v1(1775,1156.45) 1789.5,1141.95 v1(1789.5,1085.91)
  Bottom Layer w25: T3.1@1112.85,1468.91 951.15,1307.21 757.15,1307.21 ; v1(1637,1285.91) v1(1672,1285.91) 1673,1285.91 1692,1304.91 v1(1692,1471.91) v1(1720,1499.91) ; 757.15,1307.21 v1(728.85,1307.21) v1(728.85,1278.91) 757.15,1307.21
5V: C1.1 C2.2 D1.1 J1.1 J4.2 J19.1 L1.1 R1.1 R40.1 U1.1 | length 4384.3
  Top Layer w15: L1.1@564,1598.91 L1.1@571.87,1598.91 612.37,1598.91 R1.1@626,1612.54
  Top Layer w30: 691.5,1809.41 802,1919.91 1734.27,1919.91 J19.1@1739.37,1925 1795.27,1980.91 2867,1980.91 2939,1908.91 2939,1781.91 3235,1485.91 3235,533.62 3204.28,502.91 3119.54,502.91 J4.2@3048.82,573.62
  Bottom Layer w30: R40.1@2850.63,680 2957.01,573.62 J4.2@3048.82,573.62
5V/3.3VA: J19.2 J27.27 | length 512.1
  Top Layer w30: v1(1622.18,1537.91) v1(1651.18,1566.91) 1667,1582.72 1667,1752.63 J19.2@1739.37,1825
  Bottom Layer w30: J27.27@1541.98,1435.7 1541.98,1457.7 v1(1622.18,1537.91) v1(1651.18,1566.91)
AGND: C7.2 C8.1 C9.2 C10.1 C11.1 C12.1 C13.1 C14.1 C15.1 C16.1 C17.1 C20.1 C23.1 C24.1 C28.1 C29.1 C30.1 C31.1 C33.1 C35.1 C36.2 C37.2 C38.2 C40.1 C41.1 C42.1 Cali9.1 J16.1 J18.1 R5.2 R6.2 R7.2 R31.1 R33.2 R44.2 R49.2 RV2.1 T4.1 U2.2 U3.20 U7.3 U11.4 | length 1913
  Top Layer w10: 150,1063.62 150,993 162,981 ; v1(1605.5,1114.5) U3.20@1630.63,1114.5
  Top Layer w15: v1(447,763.28) C41.1@475,763.28 ; C42.1@641.57,762.63 v1(669.57,762.63) ; v1(760.37,1238.55) R31.1@760.37,1264.25 ; R5.2@763.12,1362 763.12,1406.69 C12.1@762.97,1406.84 v1(790.12,1406.84) C11.1@815,1406.84 ; v1(975.52,1445.39) C10.1@975.52,1478.91 ; U11.4@1057.53,1222.47 v1(1102.43,1222.47) ; C36.2@1189.93,1187.09 v1(1220.53,1187.09) ; R44.2@1190,905.29 v1(1190,930) ; v1(1441.77,972.61) C24.1@1466.91,972.61 ; v1(1441.77,1022.96) C23.1@1466.91,1022.96 ; v1(1441.77,1073.68) C17.1@1466.91,1073.68 ; v1(1441.77,1122.77) C16.1@1466.91,1122.77 ; v1(1570,460.91) C33.1@1598.52,460.91 ; C15.1@1615,1224.7 C20.1@1659.04,1224.7 ; 1691,1167 1701.55,1156.45 v1(1735,1156.45) C13.1@1735,1185.09 ; v1(1704.09,1185.09) C13.1@1735,1185.09 ; C20.1@1659.04,1224.7 v1(1659.04,1252.91) 1681.18,1252.91 v1(1691,1243.09) ; C20.1@1659.04,1224.7 1680.7,1224.7 1691,1235 v1(1691,1243.09) ; v1(1691,1243.09) 1721.61,1243.09 C14.1@1723.8,1240.91 1733,1231.7 1733,1187.09 C13.1@1735,1185.09
  Top Layer w20: C40.1@515,882.28 v1(550,882.28) R33.2@591.57,882.28 641.57,932.28 C31.1@641.57,939.37 ; RV2.1@552.57,507.61 552.57,573.61 C35.1@586.57,607.61 ; v1@640.26,1435.17 633.35,1442.09 C7.2@633.35,1468.91 643.35,1478.91 C8.1@689.49,1478.91 ; C30.1@642.6,1180.83 v1(674.08,1180.83) ; C28.1@651.57,1235.91 v1(689.35,1235.91) ; v1(673.54,939.37) C31.1@641.57,939.37 ; v1(677.32,1050.61) U7.3@677.32,1089.43 ; v1(690,1450.41) 689.49,1450.91 C8.1@689.49,1478.91 ; v1(693,976.91) 677.1,992.81 C29.1@651.78,992.81 641.57,982.59 C31.1@641.57,939.37 ; C37.2@760.37,1083.09 v1(760.37,1109.99) C38.2@760.37,1136.89 ; v1(785,1498.91) U2.2@745.21,1498.91 728,1498.91 708,1478.91 C8.1@689.49,1478.91 ; v1(920,1430.91) C9.2@920,1468.91 ; R49.2@1198.18,1305.02 R49.2@1199.93,1306.77 v1(1237.07,1306.77)
  Top Layer w50: J18.1@1017.52,756.14 1073.86,756.14
  Bottom Layer w10: v1@1296,1097.91 1369,1097.91
  other v1: 40,40.91 195,40.91 381,40.91 681,40.91 981,40.91 1281,40.91 1581,40.91 1802,41.91 1285,258.91 1058,277 1663,311 1443,316.91 35,336.91 1196,379.91 1795,388.91 950,407.91 1599,419 599,449 900,460.91 1693,496.91 1253,527.91 398,547.91 1372,566.91 1144,580.91 547,607 1441,625.91 35,636.91 467,642.91 293,716.91 1361,752 1269,757 1440,820.91 711.57,862.91 396,866 1371,916.91 35,936.91 418,937.91 760,977.91 547,982.91 1094,987.91 1220,1010 841,1042.91 1099,1047.91 1265,1047.91 376.62,1081.09 419.62,1081.09 469.62,1081.09 508.62,1081.09 1293,1098.91 893,1117.91 35,1134.91 1504,1181 999,1222.91 1404,1224 1576,1225 1614,1253 878,1263.91 1089,1363 810,1363.91 1180,1409.91 640,1434.91
AINN1: J12.2 J15.2 J25.3 R12.1 | length 2436.8
  Top Layer w10: J15.2@1321.46,162.35 1321.46,313.37 1321,313.83 1321,1048.98 v1(1345.7,1073.68) R12.1@1371.76,1073.68
  Bottom Layer w10: J25.3@99,913.62 147.09,961.72 362.3,961.72 410.49,1009.91 846.7,1009.91 867.52,989.09 867.52,929.39 917.52,879.39 J12.2@917.52,856.14 967.28,905.91 1075.91,905.91 1243.68,1073.68 v1(1345.7,1073.68)
AINN2: J18.2 R13.1 | length 564.9
  Top Layer w10: v1(1345.86,1022.93) R13.1@1371.91,1022.93
  Bottom Layer w10: J18.2@917.52,756.14 967.28,805.91 1110.91,805.91 1327.93,1022.93 v1(1345.86,1022.93)
AINP1: J5.2 J15.1 J25.1 J25.5 R8.1 | length 2842.4
  Top Layer w10: J25.1@99,1013.62 149,963.62 149,863.62 J25.5@99,813.62 155.24,757.39 317.61,757.39 394.09,680.91 520,680.91 560,720.91 670,720.91 719.5,770.41 ; 719.5,770.91 719.5,770.41 ; J5.2@917.52,956.14 900.24,956.14 850.59,906.5 792.59,906.5 762,875.91 762,812.91 719.5,770.41 ; J15.1@1123.07,162.35 1297,336.28 1297,1073.91 v1(1345.86,1122.77) R8.1@1371.91,1122.77
  Bottom Layer w10: J5.2@917.52,956.14 975.28,1013.91 1103.91,1013.91 1212.77,1122.77 v1(1345.86,1122.77)
AINP2: J17.2 R16.1 | length 585.3
  Top Layer w10: v1(1345.7,972.61) R16.1@1371.76,972.61
  Bottom Layer w10: J17.2@917.52,656.14 966.28,704.91 1054.91,704.91 1322.61,972.61 v1(1345.7,972.61)
BEEP: J7.2 R34.1 | length 902.3
  Top Layer w6: v1(2363,1721.91) 2529,1555.91 R34.1@2630.44,1555.91
  Bottom Layer w6: J7.2@1839.37,1824.54 1892,1771.91 2313,1771.91 v1(2363,1721.91)
CALI_0: C40.2 Cali6.1 J25.2 R32.1 R38.1 | length 453.3
  Top Layer w10: J25.2@180,999.61 J25.2@180,1014.39 ; J25.2@199,1009.39 208.77,999.61 Cali6.1@309.87,999.61 427.21,882.28 C40.2@475,882.28 ; R38.1@475,819.91 C40.2@475,882.28 ; R32.1@475,929.78 C40.2@475,882.28
CALI_1: C41.2 Cali7.1 J25.4 R37.2 R38.2 | length 577.6
  Top Layer w10: J25.4@180,906.5 J25.4@180,914.39 ; J25.4@199,909.39 306.98,909.39 Cali7.1@309.87,906.5 371,845.37 371,796.07 436.16,730.91 490,730.91 515,755.91 C41.2@515,763.28 515,819.91 R38.2@525,819.91 R37.2@591.57,819.91
CALI_2: C42.2 Cali8.1 J25.6 R33.1 R37.1 | length 612.3
  Top Layer w10: J25.6@199,809.39 305.87,809.39 Cali8.1@309.87,813.39 417.35,705.91 509.56,705.91 566.29,762.63 C42.2@601.57,762.63 R37.1@655.2,816.27 ; Cali8.1@309.87,814.39 Cali8.1@310.87,814.39 ; R37.1@651.57,819.91 R33.1@651.57,882.28 ; R37.1@654.52,822.41 R37.1@655.09,822.98
EARTH1: C43.2 HOLE1.1 J1.6 J1.7 J1.8 J1.9 J1.10 J1.11 R42.2
  other v1: 58,1679.91 489.11,1870.96 489.11,1915.64 489.11,1960.32 58,1979.91 489.11,2005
